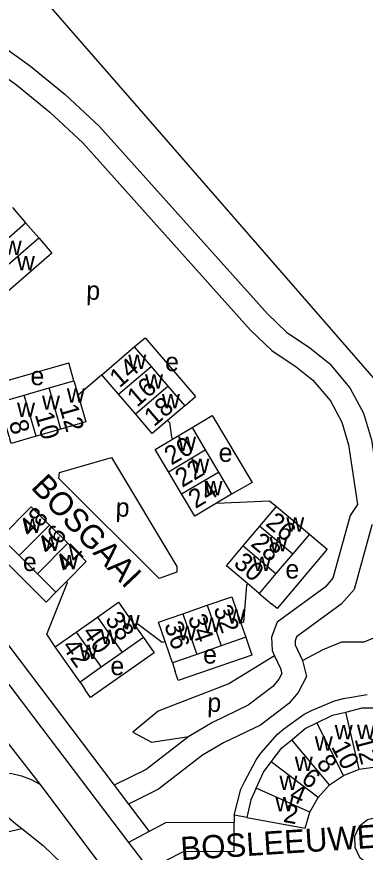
# Model space of a CAD drawing. Extents: x 155854 to 157362, y 383621 to 384685.
# Drawn here: x 156972.9 to 157047.7, y 384097.6 to 384276.9 of the extents above; entities that cross this region are included whole.
import ezdxf

# ---------------------------------------------------------------- set-up
doc = ezdxf.new("R2010")
doc.units = 0
for name, color, linetype in [('BLT_Basislijn', 7, 'Continuous'), ('BLT_Bebouwing', 7, 'Continuous'), ('BLT_Centroide', 7, 'Continuous'), ('BLT_Huisnummer', 7, 'Continuous'), ('BLT_Huisnummer_ tussenligend', 7, 'Continuous'), ('BLT_Onderverdeling_panden', 7, 'Continuous'), ('BLT_Straatnaam', 7, 'Continuous'), ('BLT_Vlakafsluiter', 7, 'Continuous')]:
    doc.layers.add(name, color=color, linetype=linetype)

msp = doc.modelspace()

# ---------------------------------------------------------------- linework, layer by layer
at = {"layer": 'BLT_Basislijn'}
for p, q in [((156986.43, 384271.78), (157000.12, 384256.08)), ((157000.12, 384256.08), (157060.4, 384186.8)), ((156879.81, 384254.13), (156976.52, 384126.62)), ((156998.14, 384206.08), (157000.44, 384208.05)), ((157000.44, 384208.05), (157011.3, 384195.41)), ((156985.2, 384198.82), (156984.09, 384202.69)), ((156991.17, 384200.12), (156986.08, 384195.75)), ((157008.99, 384193.45), (157011.3, 384195.41)), ((157035.7, 384165.93), (157039.52, 384162.71)), ((156960.45, 384156.12), (156993.84, 384112.01)), ((156981.3, 384153.46), (156979.21, 384151.32)), ((157024.96, 384153.19), (157027.68, 384150.9)), ((157000.08, 384143.73), (157002.4, 384140.47)), ((157022.06, 384143.77), (157022.79, 384141.66)), ((157006.33, 384138.31), (157006.93, 384136.4)), ((156986.49, 384134.18), (156987.58, 384132.49)), ((156993.84, 384112.01), (156996.91, 384107.96)), ((156996.91, 384107.96), (157001.35, 384102.1)), ((157022.31, 384105.11), (157019.55, 384105.61)), ((156966.33, 384101.01), (156973.99, 384102.74))]:
    msp.add_line(p, q, dxfattribs=at)
for points in [[(156870.9, 384404.38), (156986.43, 384271.78)], [(156931.15, 384308.44), (156935.05, 384303.64), (156938.05, 384298.8), (156945.7, 384290.76), (156959.68, 384277.91), (156975.88, 384266.29), (156983.29, 384260.25), (156990.7, 384253.38), (157026.7, 384213.15), (157030.78, 384209.21), (157035.83, 384205.87), (157040, 384202.49), (157044.37, 384197.32), (157047.31, 384191.85), (157049.01, 384186.14), (157050.93, 384173.32)], [(156923.6, 384300.59), (156928.11, 384304.25), (156930.97, 384300.74), (156934.08, 384295.73), (156942.19, 384287.2), (156956.52, 384274.02), (156972.84, 384262.32), (156980.01, 384256.47), (156987.13, 384249.87), (157023.1, 384209.68), (157027.64, 384205.29), (157032.87, 384201.84), (157036.48, 384198.91), (157040.21, 384194.49), (157042.67, 384189.93), (157044.12, 384185.05), (157046.03, 384172.27)], [(156968.06, 384198.08), (156984.09, 384202.69)], [(157010.53, 384188.76), (157014.84, 384191.35), (157023.41, 384177.02), (157019.02, 384174.45)], [(157005.29, 384190.29), (157005.68, 384189.83), (157006.14, 384186.68), (157006.37, 384186.3)], [(157015.79, 384172.53), (157027.18, 384173.06), (157028.62, 384171.87)], [(157046.03, 384172.27), (157044.46, 384169.89), (157040.77, 384156.47), (157039.09, 384154.56), (157028.77, 384146.99), (157027.61, 384143.82), (157027.71, 384140.96), (157028.24, 384139.83)], [(157049.19, 384167.98), (157049.07, 384167.8), (157045.29, 384154.04), (157042.49, 384150.85), (157032.95, 384143.86), (157032.64, 384143.02), (157032.67, 384142.15), (157034.24, 384138.8)], [(156979.21, 384151.32), (156967.37, 384163.08)], [(157039.52, 384162.71), (157028.8, 384149.96), (157027.68, 384150.9)], [(156981.18, 384141.72), (156979.35, 384144.48), (156983.84, 384155.53), (156983.6, 384155.78)], [(157022.46, 384155.29), (157022.19, 384154.96), (157021.59, 384147.02), (157021.01, 384146.82)], [(157004.75, 384142.9), (157004.1, 384142.68), (156998.67, 384146.73), (156998.21, 384146.4)], [(157034.24, 384138.8), (157038.65, 384141.19), (157042.69, 384142.82), (157047.48, 384142.77), (157050.02, 384143.84), (157052.89, 384145.51), (157055.6, 384145.94), (157057.17, 384145.3), (157073.18, 384136.62), (157072.57, 384142.52)], [(157002.4, 384140.47), (156988.73, 384130.85), (156987.58, 384132.49)], [(157022.79, 384141.66), (157023.38, 384139.94), (157007.58, 384134.51), (157006.93, 384136.4)], [(157034.24, 384138.8), (157035.12, 384135.35), (157033.32, 384131.93), (157031.29, 384129.55), (157025.2, 384124.94), (157017.28, 384121.1), (157012.75, 384118.45), (157003.33, 384111.17), (156996.91, 384107.96)], [(157028.24, 384139.83), (157018.41, 384133.81), (157006.56, 384129.19), (157003.24, 384127.89), (156997.86, 384123.41), (157001.81, 384121.29), (157009.82, 384122.51)], [(157028.24, 384139.83), (157029.53, 384137.05), (157029.8, 384135.98), (157029.16, 384134.76), (157027.84, 384133.21), (157022.57, 384129.22), (157014.92, 384125.52), (157009.82, 384122.51)], [(157019.55, 384105.61), (157021.03, 384111.18), (157021.75, 384112.78), (157024.29, 384117.5), (157025.32, 384118.92), (157028.88, 384122.98), (157030.23, 384124.12), (157034.57, 384127.27), (157036.15, 384128.08), (157041.12, 384130.16), (157043.03, 384130.64), (157048.13, 384131.48)], [(156976.52, 384126.62), (156996.91, 384099.73)], [(157009.82, 384122.51), (157000.66, 384115.42), (156993.84, 384112.01)], [(156967.57, 384114.62), (156969.7, 384114.71), (156971.85, 384114.52), (156973.96, 384114.04), (156975.98, 384113.29), (156977.86, 384112.29)], [(156977.86, 384112.29), (157061.57, 384000.75)], [(156969.42, 384106.83), (156970.74, 384105.49), (156972.71, 384103.76), (156973.99, 384102.74)], [(157019.55, 384105.61), (157019.55, 384104.01)], [(156973.99, 384102.74), (156978.6, 384099.1), (156982.59, 384095.26), (156992.1, 384084.49), (157007.21, 384064.72)], [(157001.24, 384094.01), (157008.7, 384097.83), (157019.59, 384097.89), (157019.55, 384104.01)], [(157019.55, 384104.01), (157004.82, 384103.96), (157001.35, 384102.1)], [(157001.35, 384102.1), (156996.91, 384099.73)], [(156996.91, 384099.73), (157001.24, 384094.01)]]:
    msp.add_lwpolyline(points, dxfattribs=at)
for points in [[(156982.12, 384179.13), (156993.22, 384182.35), (157007.28, 384158.95), (157007.25, 384157.74), (157003.48, 384156.4), (156981.92, 384177.88)], [(157050.45, 384105.18), (157048.19, 384104.63), (157046.39, 384103.15), (157045.41, 384101.03), (157045.45, 384098.71), (157046.49, 384096.62), (157048.34, 384095.2), (157050.61, 384094.72), (157052.88, 384095.27), (157054.68, 384096.75), (157055.65, 384098.87), (157055.62, 384101.2), (157054.57, 384103.28), (157052.73, 384104.7)]]:
    msp.add_lwpolyline(points, close=True, dxfattribs=at)
at = {"layer": 'BLT_Bebouwing'}
for p, q in [((156972, 384235.97), (156974.83, 384232.71)), ((156974.83, 384232.71), (156977.65, 384229.46)), ((156991.17, 384200.12), (156998.14, 384206.08)), ((156994.77, 384195.91), (156991.17, 384200.12)), ((156985.2, 384198.82), (156986.08, 384195.75)), ((157008.99, 384193.45), (157005.29, 384190.29)), ((157006.37, 384186.3), (157010.53, 384188.76)), ((157019.02, 384174.45), (157015.79, 384172.53)), ((157025.04, 384167.62), (157028.62, 384171.87)), ((157028.62, 384171.87), (157035.7, 384165.93)), ((156983.6, 384155.78), (156981.3, 384153.46)), ((157024.96, 384153.19), (157022.46, 384155.29)), ((156998.21, 384146.4), (157000.08, 384143.73)), ((157021.01, 384146.82), (157022.06, 384143.77)), ((156981.18, 384141.72), (156985.7, 384144.9)), ((157006.33, 384138.31), (157004.75, 384142.9)), ((156986.49, 384134.18), (156981.18, 384141.72)), ((157043.01, 384114.15), (157046.38, 384115.49)), ((157046.38, 384115.49), (157049.95, 384116.01)), ((157040.04, 384112.09), (157043.01, 384114.15)), ((157037.59, 384109.42), (157040.04, 384112.09)), ((157035.82, 384106.26), (157037.59, 384109.42)), ((157034.82, 384102.79), (157035.82, 384106.26)), ((157022.31, 384105.11), (157034.82, 384102.79))]:
    msp.add_line(p, q, dxfattribs=at)
for points in [[(156977.65, 384229.46), (156980.47, 384226.2)], [(156980.47, 384226.2), (156968.24, 384215.6)], [(156998.14, 384206.08), (157001.74, 384201.88)], [(157001.74, 384201.88), (157005.36, 384197.67)], [(156979.86, 384197.29), (156985.2, 384198.82)], [(157005.36, 384197.67), (157008.99, 384193.45)], [(156974.52, 384195.76), (156979.86, 384197.29)], [(156998.37, 384191.69), (156994.77, 384195.91)], [(156969.2, 384194.23), (156974.52, 384195.76)], [(156986.08, 384195.75), (156987.74, 384189.97), (156982.4, 384188.43)], [(156977.07, 384186.9), (156971.75, 384185.37), (156970.1, 384191.1)], [(157005.29, 384190.29), (157001.99, 384187.47), (156998.37, 384191.69)], [(157010.53, 384188.76), (157013.35, 384184)], [(156982.4, 384188.43), (156977.07, 384186.9)], [(157005.45, 384179.31), (157002.61, 384184.07), (157006.37, 384186.3)], [(157013.35, 384184), (157016.18, 384179.23)], [(157008.29, 384174.54), (157005.45, 384179.31)], [(157016.18, 384179.23), (157019.02, 384174.45)], [(157015.79, 384172.53), (157011.12, 384169.78), (157008.29, 384174.54)], [(156969.51, 384165.2), (156976.01, 384171.74), (156979.93, 384167.85)], [(156979.93, 384167.85), (156983.87, 384163.94)], [(157021.47, 384163.37), (157025.04, 384167.62)], [(157035.7, 384165.93), (157032.12, 384161.67)], [(156973.43, 384161.31), (156969.51, 384165.2)], [(156983.87, 384163.94), (156987.81, 384160.02), (156983.6, 384155.78)], [(157022.46, 384155.29), (157017.9, 384159.12), (157021.47, 384163.37)], [(156977.35, 384157.38), (156973.43, 384161.31)], [(157032.12, 384161.67), (157028.54, 384157.43)], [(156981.3, 384153.46), (156977.35, 384157.38)], [(157028.54, 384157.43), (157024.96, 384153.19)], [(156990.24, 384148.09), (156994.78, 384151.28), (156998.21, 384146.4)], [(157013.78, 384150.64), (157019.06, 384152.46), (157021.01, 384146.82)], [(157008.54, 384148.83), (157013.78, 384150.64)], [(156985.7, 384144.9), (156990.24, 384148.09)], [(157004.75, 384142.9), (157003.32, 384147.04), (157008.54, 384148.83)], [(157000.08, 384143.73), (156995.55, 384140.54)], [(157022.06, 384143.77), (157016.78, 384141.95)], [(156995.55, 384140.54), (156991, 384137.35)], [(157016.78, 384141.95), (157011.54, 384140.1)], [(157011.54, 384140.1), (157006.33, 384138.31)], [(156991, 384137.35), (156986.49, 384134.18)], [(157037.29, 384125.44), (157040.67, 384127.1), (157043.55, 384127.73)], [(157043.55, 384127.73), (157047.01, 384128.62), (157049.76, 384128.67)], [(157031.91, 384121.8), (157034.83, 384124.19), (157037.29, 384125.44)], [(157027.5, 384117.05), (157029.81, 384120.03), (157031.91, 384121.8)], [(157024.27, 384111.42), (157025.85, 384114.85), (157027.5, 384117.05)], [(157024.27, 384111.42), (157023.15, 384108.91), (157022.31, 384105.11)]]:
    msp.add_lwpolyline(points, dxfattribs=at)
at = {"layer": 'BLT_Onderverdeling_panden'}
for p, q in [((156962.6, 384222.12), (156974.83, 384232.71)), ((156965.42, 384218.86), (156977.65, 384229.46)), ((156994.77, 384195.91), (157001.74, 384201.88)), ((156998.37, 384191.69), (157005.36, 384197.67)), ((156982.4, 384188.43), (156979.86, 384197.29)), ((156977.07, 384186.9), (156974.52, 384195.76)), ((157005.45, 384179.31), (157013.35, 384184)), ((157008.29, 384174.54), (157016.18, 384179.23)), ((156973.43, 384161.31), (156979.93, 384167.85)), ((157025.04, 384167.62), (157032.12, 384161.67)), ((156977.35, 384157.38), (156983.87, 384163.94)), ((157021.47, 384163.37), (157028.54, 384157.43)), ((157013.78, 384150.64), (157016.78, 384141.95)), ((156990.24, 384148.09), (156995.55, 384140.54)), ((157008.54, 384148.83), (157011.54, 384140.1)), ((156985.7, 384144.9), (156991, 384137.35)), ((157046.38, 384115.49), (157043.55, 384127.73)), ((157043.01, 384114.15), (157037.29, 384125.44)), ((157040.04, 384112.09), (157031.91, 384121.8)), ((157037.59, 384109.42), (157027.5, 384117.05)), ((157035.82, 384106.26), (157024.27, 384111.42))]:
    msp.add_line(p, q, dxfattribs=at)
at = {"layer": 'BLT_Vlakafsluiter'}
msp.add_lwpolyline([(156966.22, 384127.15), (156977.86, 384112.29)], dxfattribs=at)

# ---------------------------------------------------------------- texts
at = {"layer": 'BLT_Centroide'}
for s, p in [('w', (156970.12, 384225.78)), ('w', (156972.95, 384222.53)), ('w', (156996.84, 384201.34)), ('e', (157004.75, 384200.89)), ('e', (156975.86, 384197.86)), ('w', (157000.45, 384197.12)), ('w', (156983.66, 384194.11)), ('w', (157004.06, 384192.91)), ('w', (156972.98, 384191.05)), ('w', (156978.33, 384192.58)), ('w', (157007.54, 384183.78)), ('e', (157016.24, 384181.42)), ('w', (157010.37, 384179)), ('w', (157013.2, 384174.22)), ('w', (156974.35, 384166.18)), ('w', (157030.74, 384166.47)), ('w', (156978.29, 384162.27)), ('w', (157027.16, 384162.22)), ('e', (156974.23, 384157.99)), ('w', (156982.24, 384158.37)), ('w', (157023.6, 384157.97)), ('e', (157030.56, 384156.4)), ('w', (157018.08, 384146.72)), ('w', (156995.45, 384145.51)), ('w', (157012.83, 384144.91)), ('w', (157007.58, 384143.09)), ('w', (156990.91, 384142.31)), ('w', (156986.38, 384139.12)), ('e', (157012.9, 384138.13)), ('e', (156993.01, 384135.65)), ('w', (157041.14, 384121.89)), ('w', (157045.91, 384121.94)), ('w', (157036.86, 384119.45)), ('w', (157032.57, 384115.09)), ('w', (157029.27, 384111.03)), ('w', (157028.41, 384106.41))]:
    msp.add_text(s, height=4, dxfattribs=at).set_placement(p)
for p in [(156987.78, 384216.25), (156994.09, 384169.71), (157013.76, 384127.83)]:
    msp.add_text('p', height=4, rotation=358, dxfattribs=at).set_placement(p)
at = {"layer": 'BLT_Huisnummer'}
for s, rotation, p in [('14', 40.5482, (156994.95, 384197.16)), ('18', 40.5482, (157002.36, 384188.83)), ('12', 286.0309, (156982.01, 384193.23)), ('8', 286.0309, (156971.2, 384189.83)), ('20', 30.6619, (157006.1, 384180.6)), ('24', 30.6619, (157011.26, 384171.29)), ('48', 45.1866, (156975.75, 384165.07)), ('26', 319.9648, (157026.1, 384167.92)), ('44', 45.1866, (156983.56, 384157.37)), ('30', 319.9648, (157019.23, 384159.29)), ('38', 305.1055, (156991.72, 384147.55)), ('32', 289.0069, (157015.08, 384149.97)), ('36', 289.0069, (157004.5, 384146.44)), ('42', 305.1055, (156982.47, 384141.79)), ('10', 297.7273, (157040.29, 384120.29)), ('6', 323.7282, (157033.72, 384112.84)), ('2', 349.7233, (157029.97, 384104.18))]:
    msp.add_text(s, height=4, rotation=rotation, dxfattribs=at).set_placement(p)
at = {"layer": 'BLT_Huisnummer_ tussenligend'}
for s, rotation, p in [('16', 40.5482, (156998.72, 384193.02)), ('10', 286.0309, (156976.76, 384191.58)), ('22', 30.6619, (157008.41, 384175.82)), ('46', 45.1866, (156979.71, 384161.29)), ('28', 319.9648, (157022.92, 384163.56)), ('34', 289.0069, (157009.58, 384147.99)), ('40', 305.1055, (156986.82, 384144.75)), ('12', 284.7259, (157045.39, 384121.95)), ('8', 310.7269, (157037.03, 384116.56)), ('4', 336.7274, (157031.17, 384108.9))]:
    msp.add_text(s, height=4, rotation=rotation, dxfattribs=at).set_placement(p)
at = {"layer": 'BLT_Straatnaam'}
for s, rotation, p in [('BOSGAAI', 313.4543, (156975.77, 384175.84)), ('BOSLEEUWERIK', 3.6873, (157008.21, 384095.92))]:
    msp.add_text(s, height=5, rotation=rotation, dxfattribs=at).set_placement(p)

doc.saveas('drawing.dxf')
